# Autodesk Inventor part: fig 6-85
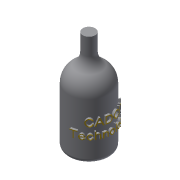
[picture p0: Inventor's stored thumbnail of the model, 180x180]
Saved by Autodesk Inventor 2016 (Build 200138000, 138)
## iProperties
Shininess: 64.0
Length Units: 11269
Angle Units: 11279
Time Units: 11290
Mass Units: 11283
Length Display Precision: 3
Angle Display Precision: 2
Compacted: True
Part Number: fig 6-85
Document SubType Name: Modeling
Created: 2002-12
Designer: deepak
Density: 1 g/cm^3
Material: Generic
Appearance: Default
Density: 0.0
Volumn: 0.0
Area: 0.0
PropertySet Name: Model Information
Control State: 0
Master: False
Checked Out: False
Author: deepak
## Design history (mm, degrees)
node "Sketch1"
sketch "Sketch2"
  geometry: L1 (-7.653, 24.992)-(-7.653, 16.776); L2 (-14.653, 3.659)-(-14.653, -3.57); L3 (-14.653, -3.57)-(-14.653, -23.329); L4 (-14.653, -23.329)-(-4.653, -23.329); L5 (-4.653, -23.329)-(-4.653, 24.992); L6 (-4.653, 24.992)-(-7.653, 24.992); A1 r 6.757 centre (-14.41, 16.776) between (-10.649, 11.163) and (-7.653, 16.776); A2 r 9.033 centre (-5.62, 3.659) between (-10.649, 11.163) and (-14.653, 3.659)
  constraints: 12 end point, 4 point on circle, 3 tangent, 2 centre point, 2 parallel, 2 perpendicular, 1 collinear, 1 vertical
  dimensions: "d0" = 3 distance of L5.end L1.start; "d1" = 10 distance of L3.end L4.end
revolve "Revolution1" sketch "Sketch2" stored, may be unused: angle "d2" = 90 deg
fillet "Fillet1" dims "d3" = 2
workplane "Work Plane1"
workplane "Work Plane2"
sketch "Sketch3"
  geometry: L1 (-24.815, -3.793)-(24.913, -3.793); L2 (24.913, -3.793)-(24.913, -8.382); L3 (24.913, -8.382)-(-24.815, -8.382); L4 (-24.815, -8.382)-(-24.815, -3.793)
  constraints: 2 other
emboss "Emboss1" sketch "Sketch3" dims "d5" = 1, "d6" = 0
body "Solid1"
other parameters: "d4" = 3.5
